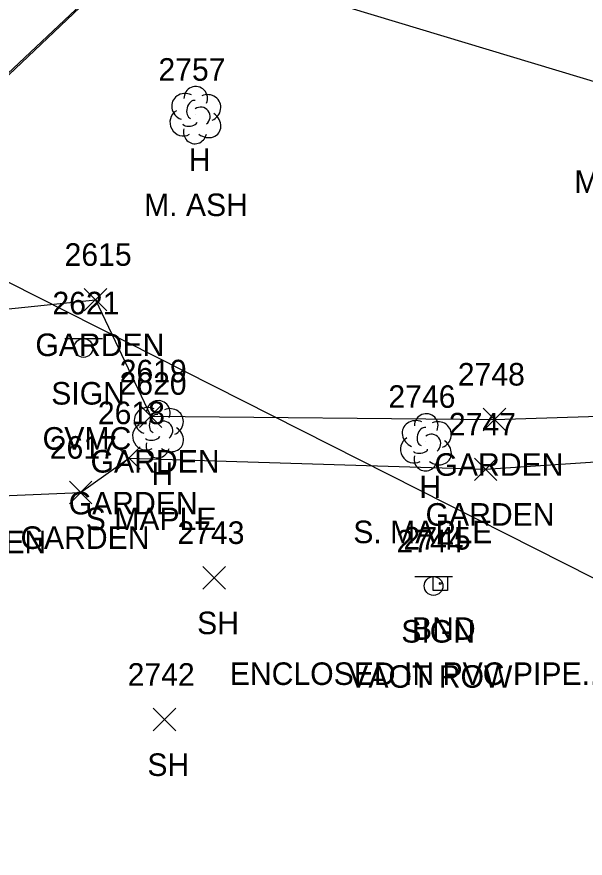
# Model space of a CAD drawing. Extents: x 1623612 to 1625808, y 621345 to 627748.
# Drawn here: x 1624644.4 to 1624694.8, y 626537 to 626611.6 of the extents above; entities that cross this region are included whole.
import ezdxf

# ---------------------------------------------------------------- set-up
doc = ezdxf.new("R2010")
doc.units = 0
for name, color, linetype in [('DCP', 7, 'Continuous'), ('L_A', 7, 'Continuous'), ('L_C', 7, 'Continuous'), ('L_I', 7, 'Continuous'), ('L_TIC', 7, 'Continuous'), ('LAPB', 7, 'Continuous'), ('Level 18', 7, 'Continuous'), ('LSOGP', 7, 'Continuous'), ('LTD', 7, 'Continuous'), ('M_A', 7, 'Continuous'), ('M_C', 7, 'Continuous'), ('M_I', 7, 'Continuous'), ('RC', 7, 'Continuous'), ('RDP', 7, 'Continuous'), ('S_A', 7, 'Continuous'), ('S_C', 7, 'Continuous'), ('S_I', 7, 'Continuous'), ('SSGN', 7, 'Continuous')]:
    doc.layers.add(name, color=color, linetype=linetype)

msp = doc.modelspace()

# ---------------------------------------------------------------- linework, layer by layer
at = {"layer": 'DCP'}
msp.add_lwpolyline([(1624498.551, 626661.392), (1624711.064, 626553.97)], dxfattribs=at)
at = {"layer": 'L_TIC'}
for points in [[(1624650.353, 626585.489), (1624652.353, 626587.489)], [(1624652.353, 626585.489), (1624650.353, 626587.489)], [(1624655.249, 626575.161), (1624657.249, 626577.161)], [(1624657.249, 626575.161), (1624655.249, 626577.161)], [(1624685.751, 626574.875), (1624687.751, 626576.875)], [(1624687.751, 626574.875), (1624685.751, 626576.875)], [(1624653.304, 626571.452), (1624655.304, 626573.452)], [(1624655.304, 626571.452), (1624653.304, 626573.452)], [(1624684.962, 626570.451), (1624686.962, 626572.451)], [(1624686.962, 626570.451), (1624684.962, 626572.451)], [(1624649.036, 626568.394), (1624651.036, 626570.394)], [(1624651.036, 626568.394), (1624649.036, 626570.394)], [(1624660.879, 626560.834), (1624662.879, 626562.834)], [(1624662.879, 626560.834), (1624660.879, 626562.834)], [(1624656.467, 626548.264), (1624658.467, 626550.264)], [(1624658.467, 626548.264), (1624656.467, 626550.264)]]:
    msp.add_lwpolyline(points, dxfattribs=at)
at = {"layer": 'LAPB'}
for points in [[(1624634.806, 626584.756), (1624640.875, 626569.007), (1624650.036, 626569.394), (1624654.304, 626572.452), (1624685.962, 626571.451), (1624706.342, 626572.836), (1624724.978, 626581.751), (1624756.443, 626634.671), (1624777.77, 626672.185), (1624774.865, 626672.505)], [(1624634.806, 626584.756), (1624651.353, 626586.489), (1624656.249, 626576.161), (1624686.751, 626575.875), (1624702.516, 626576.354), (1624721.116, 626586.23), (1624754.402, 626635.837), (1624774.865, 626672.505)]]:
    msp.add_lwpolyline(points, dxfattribs=at)
at = {"layer": 'Level 18'}
msp.add_lwpolyline([(1624681.315, 626561.957), (1624682.565, 626561.957), (1624682.565, 626560.707), (1624681.315, 626560.707)], close=True, dxfattribs=at)
msp.add_circle((1624681.94, 626561.332), 0.0833, dxfattribs=at)
at = {"layer": 'LSOGP'}
msp.add_lwpolyline([(1624698.361, 626604.96), (1624655.713, 626617.845), (1624655.68, 626617.951), (1624641.104, 626631.463), (1624640.976, 626631.67), (1624639.833, 626633.661), (1624623.152, 626641.33), (1624599.822, 626654.21), (1624598.914, 626656.803), (1624591.163, 626654.136), (1624583.412, 626651.469), (1624576.579, 626652.442), (1624569.746, 626653.414), (1624563.681, 626656.254), (1624557.616, 626659.093), (1624553.685, 626663.135), (1624549.754, 626667.178), (1624546.926, 626673.491), (1624544.099, 626679.805), (1624539.063, 626695.143), (1624536.674, 626723.203)], dxfattribs=at)
at = {"layer": 'LTD'}
for p, q in [((1624660.197, 626602.899), (1624660.197, 626602.899)), ((1624660.197, 626602.899), (1624660.197, 626602.899)), ((1624656.883, 626575.057), (1624656.883, 626575.057)), ((1624656.883, 626575.057), (1624656.883, 626575.057)), ((1624680.647, 626573.901), (1624680.647, 626573.901)), ((1624680.647, 626573.901), (1624680.647, 626573.901))]:
    msp.add_line(p, q, dxfattribs=at)
for centre in [(1624660.244, 626604.333), (1624656.93, 626576.491), (1624680.694, 626575.335)]:
    msp.add_arc(centre, 1.047, 335.52715, 180.95627, dxfattribs=at)
for centre, major_axis, ratio, start_param, end_param in [((1624659.405, 626603.565), (1.21, -0.512), 0.895232, 1.570796, 4.712389), ((1624661.239, 626603.482), (-1.141, -0.483), 0.949671, 1.570796, 4.712389), ((1624659.989, 626603.357), (-0.208, -0.792), 0.645439, 3.141593, 6.283185), ((1624660.697, 626602.732), (-0.5, 0.667), 0.989748, 3.141593, 6.283185), ((1624659.114, 626602.19), (0.584, -1.042), 0.959034, 3.141593, 6.283185), ((1624661.197, 626602.065), (-1.09, 0.792), 0.841452, 1.570796, 4.712389), ((1624659.739, 626602.149), (-0.625, -0.083), 0.423636, 0, 3.141593), ((1624660.197, 626601.399), (0.265, 1.061), 0.942809, 1.570796, 4.712389), ((1624656.091, 626575.724), (1.21, -0.512), 0.895232, 1.570796, 4.712389), ((1624657.925, 626575.641), (-1.141, -0.483), 0.949671, 1.570796, 4.712389), ((1624656.675, 626575.516), (-0.208, -0.792), 0.645439, 3.141593, 6.283185), ((1624655.8, 626574.349), (0.584, -1.042), 0.959034, 3.141593, 6.283185), ((1624657.383, 626574.891), (-0.5, 0.667), 0.989748, 3.141593, 6.283185), ((1624679.855, 626574.568), (1.21, -0.512), 0.895232, 1.570796, 4.712389), ((1624681.689, 626574.485), (-1.141, -0.483), 0.949671, 1.570796, 4.712389), ((1624657.883, 626574.224), (-1.09, 0.792), 0.841452, 1.570796, 4.712389), ((1624680.439, 626574.36), (-0.208, -0.792), 0.645439, 3.141593, 6.283185), ((1624681.147, 626573.735), (-0.5, 0.667), 0.989748, 3.141593, 6.283185), ((1624656.883, 626573.557), (0.265, 1.061), 0.942809, 1.570796, 4.712389), ((1624656.425, 626574.307), (-0.625, -0.083), 0.423636, 0, 3.141593), ((1624679.564, 626573.193), (0.584, -1.042), 0.959034, 3.141593, 6.283185), ((1624681.647, 626573.068), (-1.09, 0.792), 0.841452, 1.570796, 4.712389), ((1624680.189, 626573.151), (-0.625, -0.083), 0.423636, 0, 3.141593), ((1624680.648, 626572.401), (0.265, 1.061), 0.942809, 1.570796, 4.712389)]:
    msp.add_ellipse(centre, major_axis=major_axis, ratio=ratio, start_param=start_param, end_param=end_param, dxfattribs=at)
at = {"layer": 'RC'}
msp.add_lwpolyline([(1624655.713, 626617.845), (1624631.592, 626595.025), (1624625.693, 626589.399), (1624618.539, 626581.034), (1624613.56, 626573.771), (1624609.694, 626566.129), (1624607.962, 626559.164), (1624607.718, 626545.481), (1624608.94, 626538.058), (1624609.167, 626536.977)], dxfattribs=at)
at = {"layer": 'RDP'}
msp.add_lwpolyline([(1624655.68, 626617.951), (1624631.393, 626595.1), (1624625.545, 626589.447), (1624618.304, 626581.17), (1624613.441, 626573.989), (1624609.424, 626566.141), (1624607.751, 626559.302), (1624607.565, 626545.475), (1624608.692, 626538.102), (1624609.167, 626536.977)], dxfattribs=at)
at = {"layer": 'SSGN'}
for p, q in [((1624648.644, 626583.043), (1624651.977, 626583.043)), ((1624650.291, 626582.21), (1624650.291, 626582.21)), ((1624679.694, 626561.939), (1624683.027, 626561.939)), ((1624681.341, 626561.106), (1624681.341, 626561.106))]:
    msp.add_line(p, q, dxfattribs=at)
for centre in [(1624650.291, 626582.21), (1624681.341, 626561.106)]:
    msp.add_circle(centre, 0.833, dxfattribs=at)

# ---------------------------------------------------------------- texts
at = {"layer": 'L_A'}
for s, p in [('H', (1624659.63, 626597.899)), ('GARDEN', (1624646.022, 626581.489)), ('GARDEN', (1624650.918, 626571.161)), ('GARDEN', (1624681.421, 626570.875)), ('H', (1624656.316, 626570.057)), ('H', (1624680.08, 626568.901)), ('GARDEN', (1624648.974, 626567.452)), ('GARDEN', (1624680.632, 626566.451)), ('GARDEN', (1624644.705, 626564.394)), ('GARDEN', (1624635.544, 626564.007)), ('SH', (1624660.367, 626556.834)), ('SH', (1624655.955, 626544.264))]:
    msp.add_text(s, height=2, dxfattribs=at).set_placement(p)
at = {"layer": 'L_C'}
for s, p in [('M. ASH', (1624693.825, 626595.96)), ('M. ASH', (1624655.662, 626593.899)), ('S MAPLE', (1624650.489, 626566.057)), ('S. MAPLE', (1624674.222, 626564.901))]:
    msp.add_text(s, height=2, dxfattribs=at).set_placement(p)
at = {"layer": 'L_I'}
for s, p in [('2757', (1624656.937, 626605.899)), ('2615', (1624648.612, 626589.489)), ('2619', (1624653.501, 626579.161)), ('2748', (1624683.492, 626578.875)), ('2620', (1624653.489, 626578.057)), ('2746', (1624677.332, 626576.901)), ('2618', (1624651.564, 626575.452)), ('2747', (1624682.703, 626574.451)), ('2617', (1624647.296, 626572.394)), ('2743', (1624658.619, 626564.834)), ('2742', (1624654.207, 626552.264))]:
    msp.add_text(s, height=2, dxfattribs=at).set_placement(p)
at = {"layer": 'M_A'}
msp.add_text('BND', height=2, dxfattribs=at).set_placement((1624679.429, 626556.332))
at = {"layer": 'M_C'}
msp.add_text('ENCLOSED IN PVC PIPE...', height=2, dxfattribs=at).set_placement((1624663.263, 626552.332))
at = {"layer": 'M_I'}
msp.add_text('2745', height=2, dxfattribs=at).set_placement((1624678.681, 626564.332))
at = {"layer": 'S_A'}
for p in [(1624647.429, 626577.189), (1624678.479, 626556.086)]:
    msp.add_text('SIGN', height=2, dxfattribs=at).set_placement(p)
at = {"layer": 'S_C'}
for s, p in [('CVMC', (1624646.657, 626573.189)), ('VAOT ROW', (1624673.778, 626552.086))]:
    msp.add_text(s, height=2, dxfattribs=at).set_placement(p)
at = {"layer": 'S_I'}
for s, p in [('2621', (1624647.531, 626585.189)), ('2744', (1624678.061, 626564.086))]:
    msp.add_text(s, height=2, dxfattribs=at).set_placement(p)

doc.saveas('drawing.dxf')
